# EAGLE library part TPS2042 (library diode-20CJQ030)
Ti's TPS2042 CURRENT-LIMITED, POWER-DISTRIBUTION SWITCHES Description: The TPS204xB/TPS205xB power-distribution switches are intended for applications where heavy capacitive loads and short circuits are likely to be encountered. These devices incorporates 70-mW N-channel MOSFET power switches for power-distribution systems that require multiple power switches in a single package. Each switch is controlled by a logic enable input. Gate drive is provided by an internal charge pump designed to control the power-switch rise times and fall times to minimize current surges during switching. The charge pump requires no external components and allows operation from supplies as low as 2.7 V. When the output load exceeds the current-limit threshold or a short is present, the device limits the output current to a safe level by switching into a constant-current mode, pulling the overcurrent (OCx) logic output low. When continuous heavy overloads and short-circuits increase the power dissipation in the switch, causing the junction temperature to rise, a thermal protection circuit shuts off the switch to prevent damage. Recovery from a thermal shutdown is automatic once the device has cooled sufficiently. Internal circuitry ensures that the switch remains off until valid input voltage is present. This power-distribution switch is designed to set current limit at 1 A typically. Features: 70-mW High-Side MOSFET 500-mA Continuous Current Thermal and Short-Circuit Protection Accurate Current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
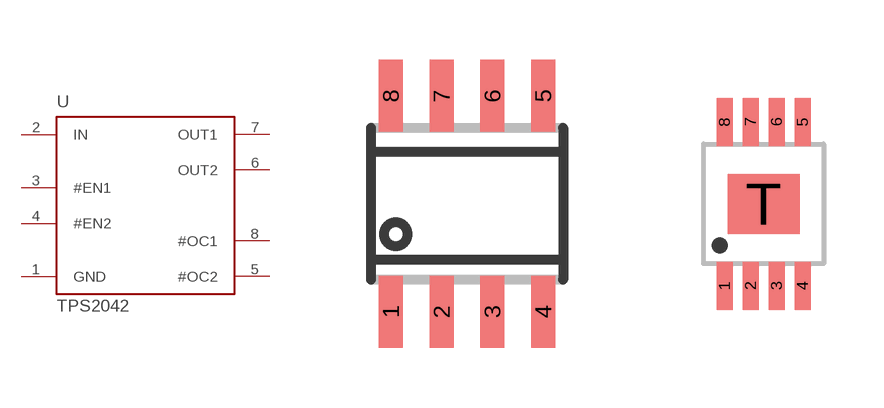
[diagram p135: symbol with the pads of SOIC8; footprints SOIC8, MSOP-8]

Designator prefix U

## TPS2042-D  [SOIC8]
1  GND  pwr
2  IN  pwr
3  #EN1  in
4  #EN2  in
5  #OC2  out
6  OUT2  out
7  OUT1  out
8  #OC1  out

## TPS2042-DGN  [MSOP-8]
Pads as for SOIC8

## Footprint SOIC8 (pad centres in mm)
Small Outline IC
smd 0.6 x 1.8: 1 -1.905,-2.7; 2 -0.635,-2.7; 3 0.635,-2.7; 4 1.905,-2.7; 5 1.905,2.7; 6 0.635,2.7; 7 -0.635,2.7; 8 -1.905,2.7

## Footprint MSOP-8 (pad centres in mm)
smd 0.4 x 1.2: 1 -0.975,-2.05; 2 -0.325,-2.05; 3 0.325,-2.05; 4 0.975,-2.05; 5 0.975,2.05; 6 0.325,2.05; 7 -0.325,2.05; 8 -0.975,2.05
smd 1.8 x 1.5: T 0,0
